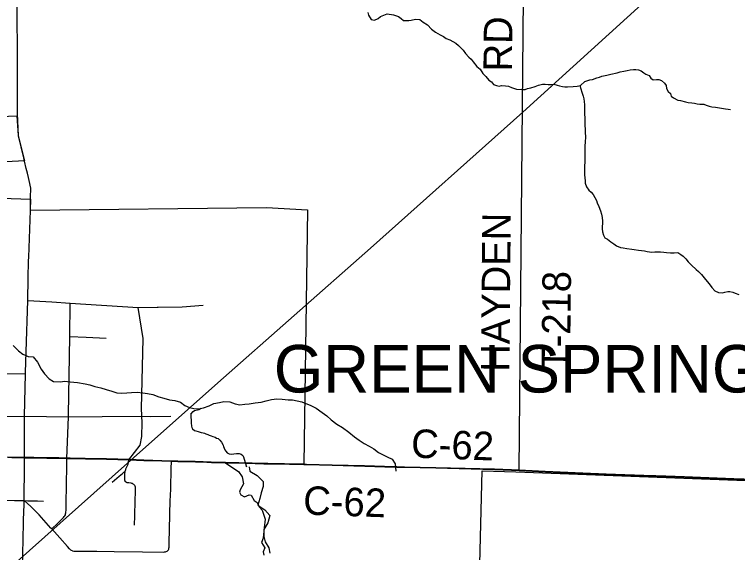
# Model space of a CAD drawing. Extents: x -8.5 to 18.7, y -20.3 to 7.
# Drawn here: x 1.387 to 4.267, y -11.043 to -8.899 of the extents above; entities that cross this region are included whole.
import ezdxf

# ---------------------------------------------------------------- set-up
doc = ezdxf.new("R2010")
doc.units = 0
for name, color, linetype in [('GM_X_City_Street', 7, 'Continuous'), ('GM_X_Corporation', 7, 'Continuous'), ('GM_X_Corporation_Text', 7, 'Continuous'), ('GM_X_County_Road', 7, 'Continuous'), ('GM_X_County_Road_Text', 7, 'Continuous'), ('GM_X_Minor_River', 7, 'Continuous'), ('GM_X_Rail_Line', 7, 'Continuous'), ('GM_X_Section', 7, 'Continuous'), ('GM_X_State_Route', 7, 'Continuous'), ('GM_X_Township', 7, 'Continuous'), ('GM_X_Township_Road', 7, 'Continuous'), ('GM_X_Township_Road_Text', 7, 'Continuous'), ('SH_Cut_Line', 7, 'Continuous')]:
    doc.layers.add(name, color=color, linetype=linetype)

msp = doc.modelspace()

# ---------------------------------------------------------------- linework, layer by layer
at = {"layer": 'GM_X_City_Street'}
for points in [[(1.4401, -10.0383), (1.5357, -10.0436), (1.6098, -10.0484), (1.8798, -10.0666), (1.9552, -10.0652), (1.9592, -10.0651)], [(1.6028, -10.4942), (1.6074, -10.182), (1.6098, -10.0484)], [(1.8947, -10.495), (1.8939, -10.47), (1.8996, -10.1896), (1.8798, -10.0666)], [(1.9592, -10.0651), (2.055, -10.0633), (2.1393, -10.0567)], [(1.6074, -10.182), (1.6729, -10.1844), (1.7531, -10.188)], [(1.1822, -10.284), (1.2591, -10.3029), (1.3106, -10.3202), (1.3502, -10.3292), (1.4311, -10.3306)], [(0.9593, -10.4974), (1.1863, -10.501), (1.4281, -10.4988), (1.6026, -10.5019), (1.737, -10.5007)], [(1.596, -10.6676), (1.6026, -10.5019), (1.6028, -10.4942)], [(1.737, -10.5007), (1.8948, -10.4991), (1.9309, -10.5001), (2.0098, -10.4988)], [(1.8426, -10.6733), (1.8875, -10.6154), (1.8951, -10.5808), (1.8963, -10.5246), (1.8948, -10.4991), (1.8947, -10.495)], [(1.5361, -10.9488), (1.5387, -10.9462), (1.5562, -10.9296), (1.5672, -10.9193), (1.5781, -10.909), (1.5833, -10.9033), (1.5861, -10.8996), (1.5881, -10.896), (1.5901, -10.8919), (1.5912, -10.8886), (1.5923, -10.8846), (1.5927, -10.8809), (1.5932, -10.8755), (1.5934, -10.8707), (1.5934, -10.8532), (1.5935, -10.8237), (1.5941, -10.797), (1.595, -10.7495), (1.5955, -10.7198), (1.5962, -10.6916), (1.596, -10.6676)], [(1.8658, -10.9339), (1.8672, -10.8965), (1.8686, -10.8352), (1.87, -10.8005), (1.8698, -10.7892), (1.8695, -10.7853), (1.8693, -10.7832), (1.869, -10.7811), (1.8685, -10.7793), (1.8678, -10.7777), (1.8669, -10.7758), (1.8656, -10.7741), (1.8643, -10.7725), (1.8627, -10.7712), (1.8609, -10.77), (1.8593, -10.769), (1.8575, -10.7682), (1.8551, -10.7673), (1.8517, -10.7667), (1.8435, -10.7656), (1.8393, -10.7651), (1.837, -10.7647), (1.8351, -10.7641), (1.8336, -10.7635), (1.8322, -10.7625), (1.831, -10.7614), (1.8301, -10.7604), (1.829, -10.759), (1.8281, -10.7576), (1.8273, -10.7556), (1.8269, -10.7531), (1.8268, -10.751), (1.8267, -10.7463), (1.8268, -10.7393), (1.8269, -10.7312), (1.8274, -10.7256), (1.8282, -10.7205), (1.8287, -10.7184), (1.8296, -10.7154), (1.8306, -10.712), (1.8313, -10.7097), (1.8326, -10.7066), (1.8359, -10.6992), (1.84, -10.6901), (1.841, -10.6874), (1.8416, -10.6849), (1.8421, -10.681), (1.8426, -10.6733)], [(1.9987, -11.035), (2.0005, -11.0322), (2.0017, -11.0289), (2.0025, -11.025), (2.003, -11.0207), (2.0039, -10.9985), (2.0047, -10.9549), (2.0066, -10.8878), (2.0082, -10.8375), (2.0097, -10.7904), (2.0122, -10.7055), (2.0128, -10.683), (2.0129, -10.6792)], [(1.7767, -10.7619), (1.8044, -10.7386), (1.8173, -10.7275), (1.8216, -10.724), (1.8235, -10.7226), (1.826, -10.7211), (1.8282, -10.7205)], [(0.8886, -10.8456), (0.906, -10.8459), (0.9137, -10.8452), (0.919, -10.8444), (0.9248, -10.8426), (0.9319, -10.84), (0.9388, -10.8371), (0.9481, -10.8344), (0.957, -10.8326), (0.9641, -10.8315), (0.9738, -10.8307), (0.9834, -10.8304), (0.9884, -10.8303), (1.0107, -10.83), (1.0579, -10.831), (1.0965, -10.8312), (1.1574, -10.8316), (1.1895, -10.8317), (1.2281, -10.8319), (1.299, -10.8334), (1.3878, -10.8352), (1.4261, -10.8355)], [(1.6184, -11.0365), (1.6152, -11.0348), (1.6125, -11.0328), (1.6071, -11.0279), (1.5987, -11.018), (1.5684, -10.9835), (1.5361, -10.9488), (1.5328, -10.9453), (1.4855, -10.8929), (1.4649, -10.8717), (1.4523, -10.8589), (1.4261, -10.8355)], [(1.4261, -10.8355), (1.4405, -10.8362), (1.458, -10.8366), (1.4787, -10.8371), (1.5029, -10.8377)], [(1.6184, -11.0365), (1.6234, -11.0375), (1.6369, -11.0377), (1.6606, -11.0378), (1.7151, -11.0379), (1.7847, -11.0382), (1.8972, -11.0399), (1.9818, -11.0407), (1.9857, -11.0405), (1.9889, -11.0399), (1.9923, -11.0391), (1.9954, -11.0375), (1.9987, -11.035)]]:
    msp.add_lwpolyline(points, dxfattribs=at)
at = {"layer": 'GM_X_Corporation'}
for points in [[(1.2642, -9.3076), (1.3973, -9.3029), (1.4026, -9.381), (1.4272, -9.4823), (1.2561, -9.4913)], [(1.2586, -9.6281), (1.4512, -9.6345), (1.4506, -9.6788), (2.3916, -9.6676), (2.554, -9.6771), (2.5399, -10.691), (2.3872, -10.6874), (2.2283, -10.6836), (2.2258, -10.6836), (2.2793, -10.7196), (2.2946, -10.7407), (2.2991, -10.7688), (2.2866, -10.7922), (2.2837, -10.8024), (2.2894, -10.8122), (2.3035, -10.821), (2.3225, -10.8126), (2.33, -10.8136), (2.342, -10.8351), (2.3542, -10.8434), (2.3616, -10.86), (2.3745, -10.8739), (2.3787, -10.886), (2.3861, -10.9103), (2.3826, -10.9446), (2.3776, -10.9848), (2.3713, -11.0031), (2.3845, -11.0234), (2.3783, -11.0397), (2.3813, -11.0538)], [(4.3325, -10.7515), (4.2528, -10.7486), (4.1201, -10.7437), (4.0567, -10.7413), (3.9822, -10.7386), (3.9424, -10.7371), (3.894, -10.736), (3.7436, -10.7302), (3.6517, -10.726), (3.5015, -10.7194), (3.3974, -10.7148), (3.3673, -10.7135), (3.299, -10.711), (3.0654, -10.7047), (2.9411, -10.702), (2.91, -10.7017), (2.8615, -10.7001), (2.782, -10.6974), (2.6528, -10.694), (2.5509, -10.6913), (2.5399, -10.691), (2.4255, -10.6887), (2.3969, -10.6881), (2.3807, -10.6877), (2.2258, -10.6836), (2.1713, -10.6823), (2.1075, -10.6805), (2.0377, -10.6786), (2.0125, -10.6781), (1.9749, -10.6768), (1.9028, -10.6743), (1.8421, -10.6722), (1.7986, -10.6708), (1.7539, -10.6694), (1.6693, -10.6679), (1.6098, -10.6668), (1.5956, -10.6665), (1.564, -10.6659), (1.5153, -10.665), (1.4649, -10.664), (1.4265, -10.6639), (1.3594, -10.6624)]]:
    msp.add_lwpolyline(points, dxfattribs=at)
at = {"layer": 'GM_X_County_Road'}
for p, q in [((1.3776, -10.6639), (1.4269, -10.665)), ((2.2262, -10.6847), (2.3107, -10.6869))]:
    msp.add_line(p, q, dxfattribs=at)
for points in [[(1.4269, -10.665), (1.4653, -10.6651), (1.5158, -10.6661), (1.5644, -10.667), (1.596, -10.6676)], [(1.596, -10.6676), (1.6103, -10.6679), (1.6698, -10.669), (1.7543, -10.6705), (1.799, -10.6719), (1.8426, -10.6733)], [(1.8426, -10.6733), (1.9033, -10.6754), (1.9754, -10.6779), (2.0129, -10.6792)], [(2.0129, -10.6792), (2.0381, -10.6797), (2.1079, -10.6816), (2.1532, -10.6829)], [(2.1532, -10.6829), (2.1718, -10.6834), (2.2262, -10.6847)], [(2.3107, -10.6869), (2.3812, -10.6888), (2.3973, -10.6892), (2.3992, -10.6893)], [(2.3992, -10.6893), (2.4259, -10.6899), (2.5403, -10.6921)], [(2.5403, -10.6921), (2.5513, -10.6924), (2.6532, -10.6951), (2.7825, -10.6986), (2.862, -10.7012), (2.9105, -10.7028), (2.9416, -10.7031), (3.0658, -10.7058), (3.2994, -10.7121), (3.3678, -10.7146), (3.3979, -10.7159)], [(3.3979, -10.7159), (3.5019, -10.7205), (3.6522, -10.7271), (3.7441, -10.7313), (3.8944, -10.7371), (3.9429, -10.7382), (3.9826, -10.7397), (4.0572, -10.7424), (4.1205, -10.7448), (4.2532, -10.7497), (4.3329, -10.7526)]]:
    msp.add_lwpolyline(points, dxfattribs=at)
at = {"layer": 'GM_X_Minor_River'}
for points in [[(2.795, -8.8904), (2.7971, -8.9018), (2.8083, -8.9186), (2.8212, -8.9211), (2.8364, -8.9144), (2.8456, -8.9061), (2.8723, -8.8958), (2.8965, -8.8999), (2.9056, -8.9022), (2.9169, -8.9061), (2.9274, -8.9146), (2.9365, -8.9223), (2.9585, -8.9225), (2.9676, -8.9219), (2.9843, -8.9167), (3.0017, -8.9184), (3.0153, -8.9292), (3.0326, -8.9393), (3.0483, -8.9569), (3.0649, -8.9685), (3.083, -8.9801), (3.0966, -8.987), (3.1071, -8.9947), (3.1214, -8.9994), (3.1335, -9.0057), (3.1456, -9.0126), (3.1561, -9.0218), (3.1651, -9.0318), (3.1748, -9.041), (3.1838, -9.054), (3.1973, -9.0686), (3.2063, -9.077), (3.2145, -9.087), (3.2295, -9.1061), (3.243, -9.1169), (3.2527, -9.1337), (3.2654, -9.1452), (3.2767, -9.1598), (3.2872, -9.1675), (3.2954, -9.1782), (3.3075, -9.1814), (3.3174, -9.1838), (3.3272, -9.1823), (3.3431, -9.1833), (3.3553, -9.1849), (3.3666, -9.1896), (3.3757, -9.1927), (3.387, -9.1959), (3.409, -9.1977), (3.4219, -9.1978), (3.431, -9.1933), (3.444, -9.1904), (3.4615, -9.1861), (3.4752, -9.1809), (3.4904, -9.1765)], [(3.4904, -9.1765), (3.5018, -9.1766), (3.5132, -9.1775), (3.5238, -9.1776), (3.5352, -9.177), (3.5488, -9.1809), (3.5578, -9.1833), (3.5707, -9.1857), (3.5798, -9.1866), (3.5904, -9.1867), (3.6132, -9.1854), (3.6291, -9.1841), (3.6421, -9.1812), (3.6597, -9.1662), (3.6795, -9.1596), (3.6901, -9.1574), (3.7069, -9.1507), (3.7183, -9.1486), (3.7275, -9.1449), (3.7472, -9.1405), (3.7632, -9.1369), (3.7875, -9.1311), (3.8005, -9.1274), (3.8149, -9.1246), (3.8279, -9.1224), (3.8393, -9.1195), (3.8529, -9.1181), (3.862, -9.1182), (3.8734, -9.1199), (3.8832, -9.1238), (3.8938, -9.1307), (3.9028, -9.1361), (3.9149, -9.1416), (3.9216, -9.1523), (3.9314, -9.1585), (3.9443, -9.1578), (3.9542, -9.1572), (3.964, -9.1618), (3.976, -9.1718), (3.9827, -9.1818), (3.9841, -9.1932), (3.9908, -9.2062), (3.9998, -9.2139), (4.0035, -9.2238), (4.0125, -9.2314), (4.0291, -9.24), (4.0397, -9.2416), (4.0601, -9.2464), (4.0714, -9.2495), (4.0851, -9.2504), (4.0957, -9.2521), (4.1063, -9.2552), (4.1176, -9.2561), (4.1336, -9.2563), (4.1426, -9.2594), (4.154, -9.2641), (4.1646, -9.2665), (4.1797, -9.2682), (4.204, -9.2715), (4.2191, -9.2747), (4.2297, -9.2755), (4.2396, -9.2772)], [(3.6394, -9.1818), (3.6471, -9.2086), (3.6522, -9.2238), (3.6551, -9.2352), (3.6565, -9.2451), (3.6579, -9.2588), (3.6575, -9.2899), (3.6587, -9.3172), (3.6592, -9.3423), (3.6606, -9.3545), (3.6612, -9.3689), (3.6617, -9.3864), (3.6607, -9.4076), (3.6598, -9.422), (3.6596, -9.4456), (3.6586, -9.463), (3.6579, -9.526), (3.6585, -9.5374), (3.6591, -9.5496), (3.6605, -9.5617), (3.6604, -9.5709), (3.6663, -9.5861), (3.6745, -9.5991), (3.685, -9.6068), (3.6925, -9.616), (3.6984, -9.6282), (3.7051, -9.6404), (3.7088, -9.6496), (3.7155, -9.6633), (3.7214, -9.6816), (3.7258, -9.6938), (3.7286, -9.7082), (3.7292, -9.7219), (3.7289, -9.7523), (3.7295, -9.7652), (3.7332, -9.7774), (3.7391, -9.7881), (3.7489, -9.7935), (3.7632, -9.805), (3.7752, -9.812), (3.7858, -9.8205), (3.8016, -9.8267), (3.8115, -9.8291), (3.8266, -9.8315), (3.8463, -9.8333), (3.8554, -9.8356), (3.8728, -9.8373), (3.8849, -9.839), (3.8963, -9.8406), (3.9069, -9.843), (3.9167, -9.8439), (3.9258, -9.8455), (3.938, -9.8449), (3.96, -9.8451), (3.9744, -9.846), (3.985, -9.8469), (4.0009, -9.8486), (4.0146, -9.8487), (4.029, -9.8474), (4.041, -9.8551), (4.0508, -9.8613), (4.0613, -9.8728), (4.0703, -9.8842), (4.0838, -9.8981), (4.1026, -9.915), (4.1123, -9.9234), (4.1243, -9.9349), (4.1348, -9.948), (4.1468, -9.9633), (4.1543, -9.9725), (4.1647, -9.9862), (4.1767, -9.9993), (4.191, -10.0063), (4.2077, -10.0072), (4.2169, -10.005), (4.2283, -10.0021), (4.2374, -10.0022), (4.2487, -10.0054), (4.2578, -10.0093), (4.2721, -10.0147)], [(1.3817, -10.2175), (1.4035, -10.239), (1.4208, -10.2521), (1.4419, -10.2615), (1.4624, -10.2632), (1.4788, -10.2846), (1.4944, -10.3114), (1.5071, -10.3305), (1.5251, -10.3504), (1.5424, -10.3605), (1.569, -10.3623), (1.5887, -10.3602), (1.6099, -10.3627), (1.638, -10.3653), (1.669, -10.371), (1.6872, -10.375), (1.7076, -10.3813), (1.731, -10.3868), (1.753, -10.3931), (1.7756, -10.4002), (1.7953, -10.4057), (1.8157, -10.4082), (1.8355, -10.4062), (1.8537, -10.4048), (1.8765, -10.4036), (1.8992, -10.4069), (1.9174, -10.4086), (1.9386, -10.4126), (1.9628, -10.422), (1.9824, -10.4282), (2.0051, -10.4338), (2.0263, -10.4371), (2.0482, -10.4434), (2.0655, -10.4565), (2.0844, -10.465), (2.1018, -10.469), (2.1215, -10.47), (2.1405, -10.4656), (2.1634, -10.4575), (2.1817, -10.4494), (2.2037, -10.4451), (2.222, -10.4407), (2.2455, -10.4425), (2.2667, -10.4495), (2.2856, -10.4535), (2.3046, -10.4514), (2.3228, -10.4501), (2.3463, -10.4466), (2.3707, -10.4438), (2.3897, -10.4379), (2.4118, -10.4329), (2.433, -10.4301), (2.4542, -10.4318), (2.477, -10.4336), (2.4952, -10.4345), (2.5141, -10.4378), (2.5315, -10.4425), (2.5678, -10.4566), (2.5896, -10.4674), (2.6137, -10.4844), (2.631, -10.4975), (2.649, -10.5136), (2.6716, -10.5306), (2.6942, -10.5445), (2.719, -10.5637), (2.7416, -10.5814), (2.7604, -10.5945), (2.7807, -10.6076)], [(2.0898, -10.4913), (2.0991, -10.4802), (2.1052, -10.4765), (2.1159, -10.4737), (2.122, -10.4723), (2.1281, -10.4694), (2.1304, -10.468)], [(2.0895, -10.4905), (2.0902, -10.5065), (2.0909, -10.5126), (2.0907, -10.5202), (2.0914, -10.5255), (2.0926, -10.5392), (2.094, -10.5445), (2.0969, -10.5499), (2.1043, -10.5561), (2.1104, -10.5578), (2.1186, -10.561), (2.1314, -10.5643), (2.1397, -10.5659), (2.145, -10.5676), (2.1502, -10.5699), (2.157, -10.5724), (2.163, -10.5747), (2.1705, -10.5772), (2.1773, -10.5803), (2.1863, -10.5828), (2.1923, -10.5867), (2.1983, -10.5884), (2.205, -10.5946), (2.2124, -10.6023), (2.2182, -10.6145), (2.2204, -10.6199), (2.2254, -10.6329), (2.2291, -10.639), (2.235, -10.6452), (2.2432, -10.6499), (2.2523, -10.6501), (2.2606, -10.6495), (2.2713, -10.6475), (2.2826, -10.6477), (2.2909, -10.6509), (2.2969, -10.6556), (2.2998, -10.6609), (2.3026, -10.6701), (2.3113, -10.7014), (2.3084, -10.6854)], [(2.7807, -10.6076), (2.7996, -10.6185), (2.8184, -10.6301), (2.8372, -10.6439), (2.8719, -10.661), (2.8923, -10.6711), (2.9035, -10.6894), (2.9061, -10.7186)], [(2.3222, -10.7016), (2.325, -10.7189), (2.3536, -10.7358), (2.3777, -10.7602), (2.3783, -10.7799), (2.3706, -10.8049), (2.3644, -10.8276), (2.3574, -10.8534), (2.3845, -10.8725), (2.4041, -10.8954), (2.3971, -10.9241), (2.381, -10.9514), (2.3801, -10.9794), (2.386, -10.9999), (2.401, -11.0235), (2.4046, -11.0448)]]:
    msp.add_lwpolyline(points, dxfattribs=at)
at = {"layer": 'GM_X_Rail_Line'}
for points in [[(1.838, -10.6862), (2.1974, -10.3661), (2.8053, -9.8305), (3.4123, -9.2873), (4.0286, -8.7279), (4.7575, -8.0687), (5.3952, -7.4956), (6.8786, -6.1515), (7.9737, -5.1713), (8.488, -4.679), (8.8174, -4.395), (9.2327, -4.0082), (9.3799, -3.8857)], [(0.878, -11.6305), (0.9425, -11.5459), (1.0004, -11.4756), (1.0916, -11.367), (1.3117, -11.1541), (1.838, -10.6862)]]:
    msp.add_lwpolyline(points, dxfattribs=at)
at = {"layer": 'GM_X_Section'}
msp.add_lwpolyline([(3.3838, -10.7208), (5.3205, -10.7946), (5.2797, -12.6788), (3.2006, -12.6781), (3.25, -10.7172)], close=True, dxfattribs=at)
at = {"layer": 'GM_X_State_Route'}
for points in [[(1.399, -9.2938), (1.398, -8.6543)], [(1.4244, -9.4701), (1.403, -9.3821), (1.399, -9.2938)], [(1.4433, -9.5479), (1.4396, -9.5316), (1.4346, -9.5125), (1.4276, -9.4834), (1.4244, -9.4701)], [(1.4517, -9.6275), (1.4521, -9.5913), (1.4461, -9.5601), (1.4433, -9.5479)], [(1.4512, -9.6664), (1.4516, -9.6356), (1.4517, -9.6275)], [(1.4444, -9.8662), (1.4511, -9.6799), (1.4512, -9.6664)], [(1.4313, -10.3247), (1.4338, -10.2433), (1.4401, -10.0383), (1.4417, -9.9497), (1.4439, -9.8802), (1.4444, -9.8662)], [(1.4269, -10.665), (1.4281, -10.4988), (1.4311, -10.3306), (1.4313, -10.3247)], [(1.4255, -10.8513), (1.4261, -10.8355), (1.4266, -10.8121), (1.4273, -10.7199), (1.4269, -10.665)], [(1.4133, -11.0982), (1.4159, -11.0914), (1.4183, -11.084), (1.4194, -11.0788), (1.4201, -11.074), (1.4204, -11.0686), (1.4208, -11.0633), (1.4209, -11.056), (1.4211, -11.0501), (1.4214, -11.0375), (1.4221, -11.0007), (1.4233, -10.9128), (1.4255, -10.8513)]]:
    msp.add_lwpolyline(points, dxfattribs=at)
at = {"layer": 'GM_X_Township'}
msp.add_lwpolyline([(4.3325, -10.7515), (4.2528, -10.7486), (4.1201, -10.7437), (4.0567, -10.7413), (3.9822, -10.7386), (3.9424, -10.7371), (3.894, -10.736), (3.7436, -10.7302), (3.6517, -10.726), (3.5015, -10.7194), (3.3974, -10.7148), (3.3673, -10.7135), (3.299, -10.711), (3.0654, -10.7047), (2.9411, -10.702), (2.91, -10.7017), (2.8615, -10.7001), (2.782, -10.6974), (2.6528, -10.694), (2.5509, -10.6913), (2.5399, -10.691), (2.4255, -10.6887), (2.3969, -10.6881), (2.3807, -10.6877), (2.2258, -10.6836), (2.1713, -10.6823), (2.1075, -10.6805), (2.0377, -10.6786), (2.0125, -10.6781), (1.9749, -10.6768), (1.9028, -10.6743), (1.8421, -10.6722), (1.7986, -10.6708), (1.7539, -10.6694), (1.6693, -10.6679), (1.6098, -10.6668), (1.5956, -10.6665), (1.564, -10.6659), (1.5153, -10.665), (1.4649, -10.664), (1.4265, -10.6639), (1.3594, -10.6624)], dxfattribs=at)
at = {"layer": 'GM_X_Township_Road'}
msp.add_line((3.3979, -10.7159), (3.4162, -8.7161), dxfattribs=at)
at = {"layer": 'SH_Cut_Line'}
for points in [[(4.3325, -10.7515), (4.2528, -10.7486), (4.1201, -10.7437), (4.0567, -10.7413), (3.9822, -10.7386), (3.9424, -10.7371), (3.894, -10.736), (3.7436, -10.7302), (3.6517, -10.726), (3.5015, -10.7194), (3.3974, -10.7148), (3.3673, -10.7135), (3.299, -10.711), (3.0654, -10.7047), (2.9411, -10.702), (2.91, -10.7017), (2.8615, -10.7001), (2.782, -10.6974), (2.6528, -10.694), (2.5509, -10.6913), (2.5399, -10.691), (2.4255, -10.6887), (2.3969, -10.6881), (2.3807, -10.6877), (2.2258, -10.6836), (2.1713, -10.6823), (2.1075, -10.6805), (2.0377, -10.6786), (2.0125, -10.6781), (1.9749, -10.6768), (1.9028, -10.6743), (1.8421, -10.6722), (1.7986, -10.6708), (1.7539, -10.6694), (1.6693, -10.6679), (1.6098, -10.6668), (1.5956, -10.6665), (1.564, -10.6659), (1.5153, -10.665), (1.4649, -10.664), (1.4265, -10.6639), (1.3594, -10.6624)], [(1.3594, -10.6624), (1.4265, -10.6639), (1.4649, -10.664), (1.5153, -10.665), (1.564, -10.6659), (1.5956, -10.6665), (1.6098, -10.6668), (1.6693, -10.6679), (1.7539, -10.6694), (1.7986, -10.6708), (1.8421, -10.6722), (1.9028, -10.6743), (1.9749, -10.6768), (2.0125, -10.6781), (2.0377, -10.6786), (2.1075, -10.6805), (2.1713, -10.6823), (2.2258, -10.6836), (2.3807, -10.6877), (2.3969, -10.6881), (2.4255, -10.6887), (2.5399, -10.691), (2.5509, -10.6913), (2.6528, -10.694), (2.782, -10.6974), (2.8615, -10.7001), (2.91, -10.7017), (2.9411, -10.702), (3.0654, -10.7047), (3.299, -10.711), (3.3673, -10.7135), (3.3974, -10.7148), (3.5015, -10.7194), (3.6517, -10.726), (3.7436, -10.7302), (3.894, -10.736), (3.9424, -10.7371), (3.9822, -10.7386), (4.0567, -10.7413), (4.1201, -10.7437), (4.2528, -10.7486), (4.3325, -10.7515)]]:
    msp.add_lwpolyline(points, dxfattribs=at)

# ---------------------------------------------------------------- texts
at = {"layer": 'GM_X_Corporation_Text'}
msp.add_text('GREEN SPRINGS', height=0.189394, rotation=0, dxfattribs=at).set_placement((2.4204, -10.405))
at = {"layer": 'GM_X_County_Road_Text'}
for rotation, p in [(357.9065, (2.966, -10.6641)), (358.0036, (2.5361, -10.891))]:
    msp.add_text('C-62', height=0.11364, rotation=rotation, dxfattribs=at).set_placement(p)
at = {"layer": 'GM_X_Township_Road_Text'}
for s, rotation, p in [('RD', 89.5063, (3.3689, -9.1261)), ('HAYDEN', 89.512, (3.3589, -10.3227)), ('T-218', 89.4386, (3.6004, -10.3184))]:
    msp.add_text(s, height=0.11364, rotation=rotation, dxfattribs=at).set_placement(p)

doc.saveas('drawing.dxf')
